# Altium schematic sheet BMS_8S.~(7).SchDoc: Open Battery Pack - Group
size A3; Author: Morgane Vallée; Revision: 1.0; SheetNumber: 2; SheetTotal: 3
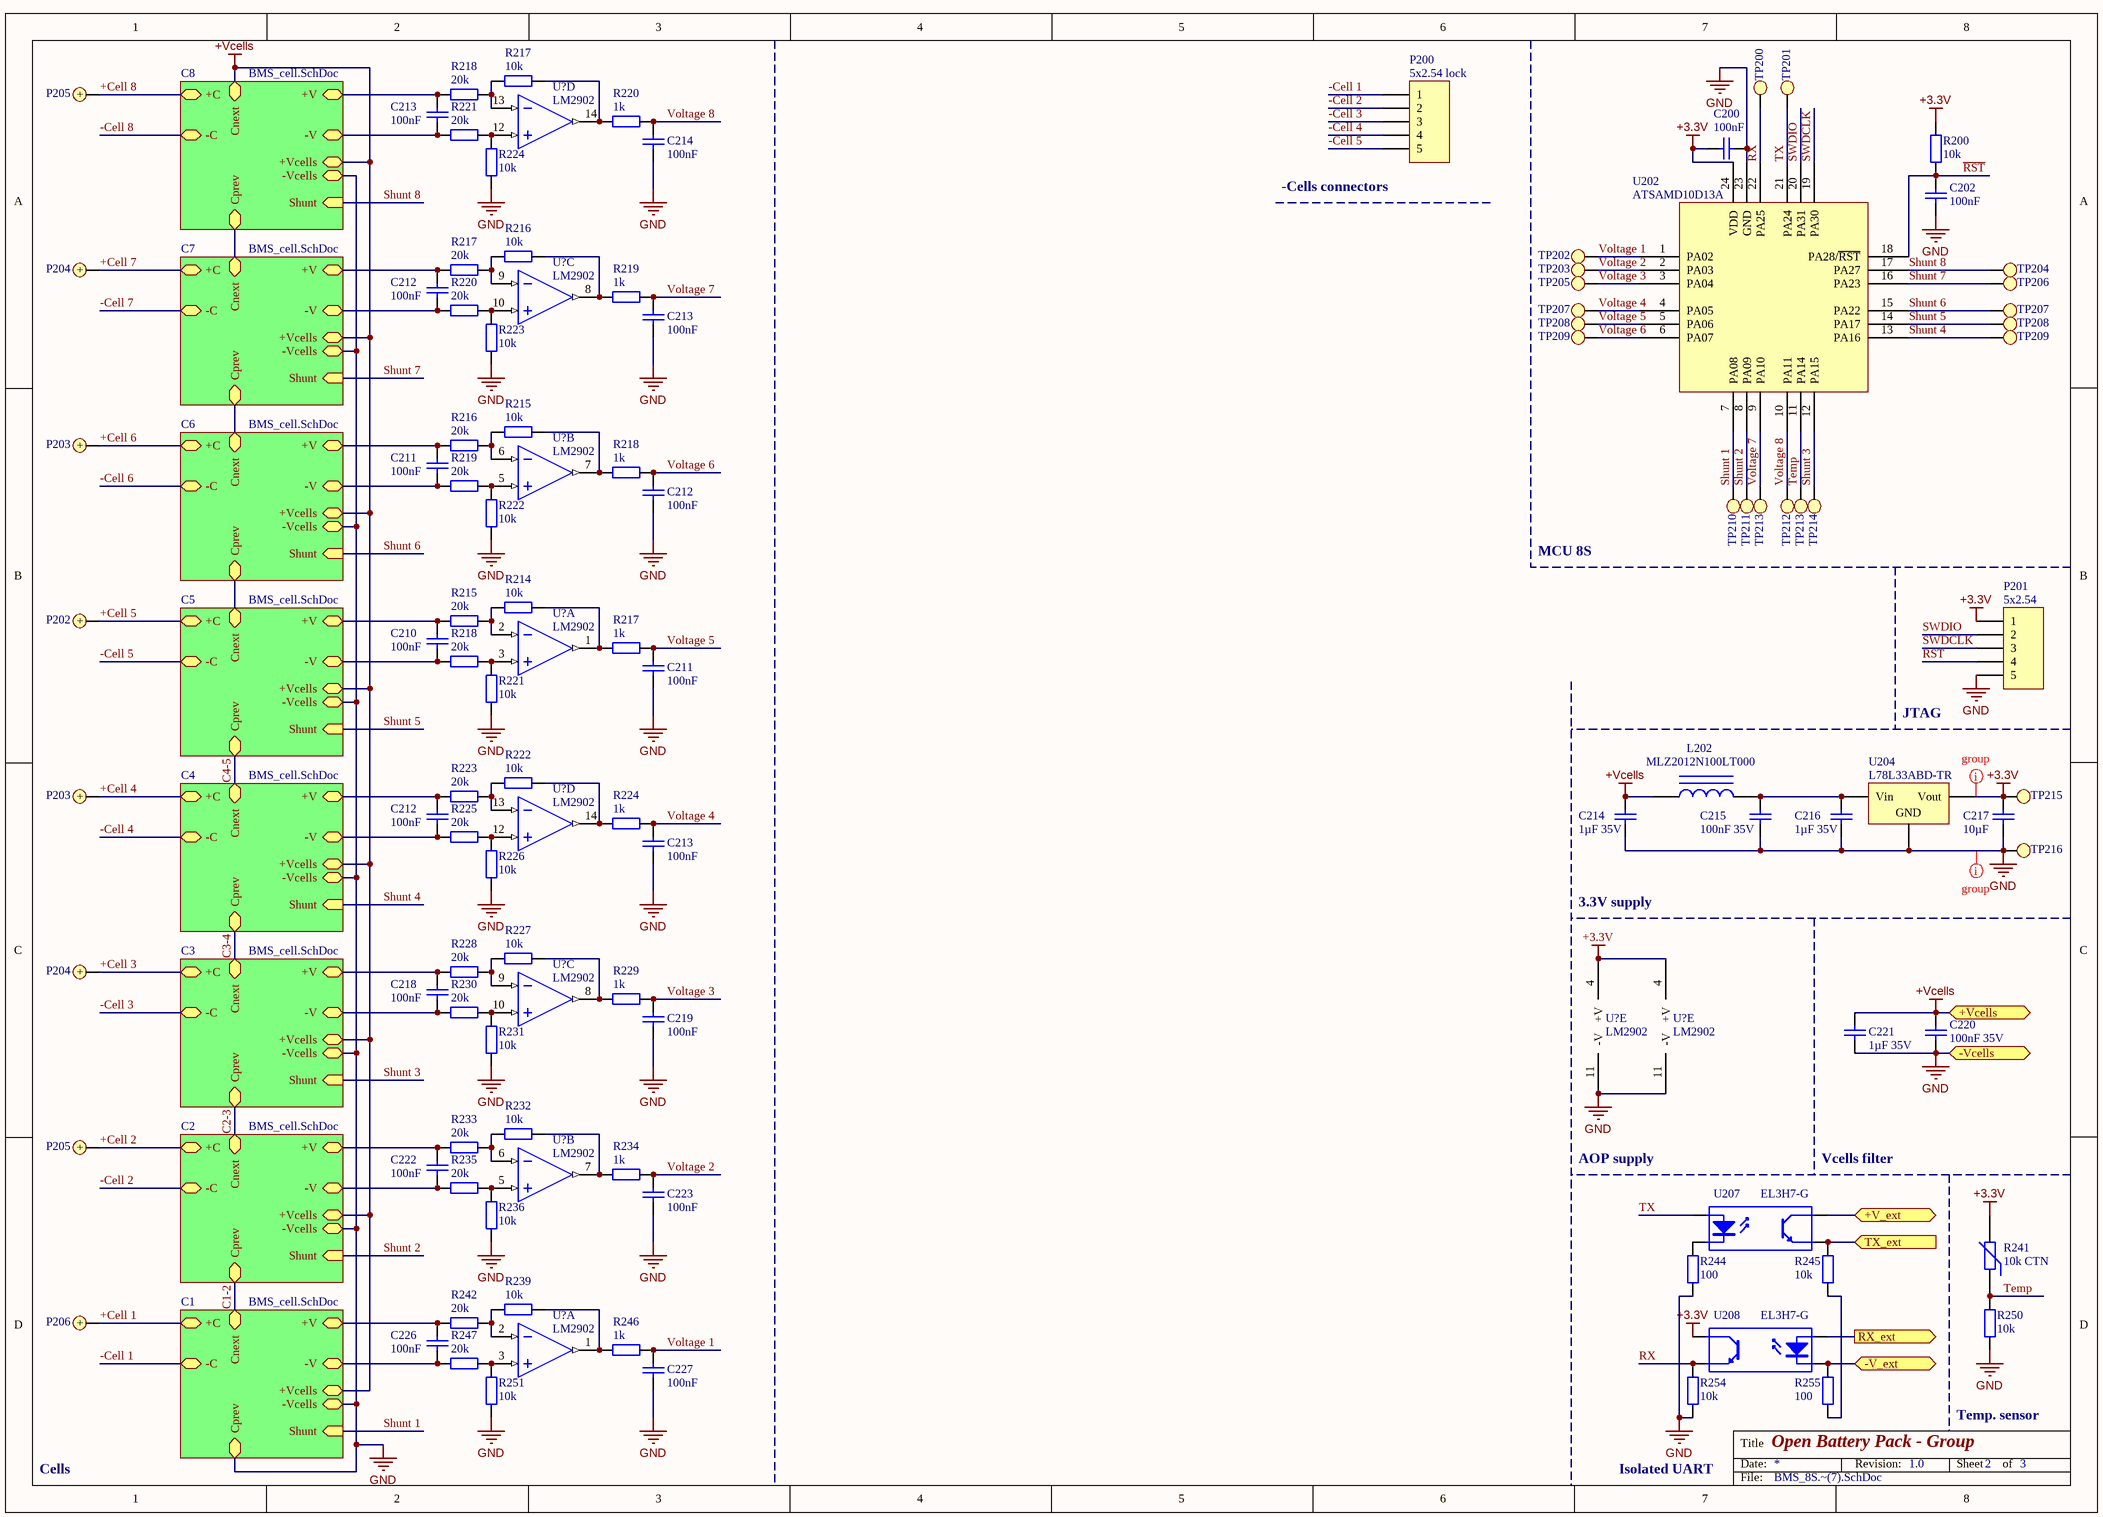
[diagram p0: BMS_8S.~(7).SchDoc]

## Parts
(Parts that share a designator on the sheet are numbered #1, #2 ... from top to bottom, then left to right.)
C200  100nF  [C0603]
C202  100nF  [C0603]
C210  100nF  [C0603]
C211#1  100nF  [C0603]
C211#2  100nF  [C0603]
C212#1  100nF  [C0603]
C212#2  100nF  [C0603]
C212#3  100nF  [C0603]
C213#1  100nF  [C0603]
C213#2  100nF  [C0603]
C213#3  100nF  [C0603]
C214#1  100nF  [C0603]
C214#2  1µF 35V  [C0805]
C215  100nF 35V  [C0603]
C216  1µF 35V  [C0805]
C217  10µF  [C0603]
C218  100nF  [C0603]
C219  100nF  [C0603]
C220  100nF 35V  [C0603]
C221  1µF 35V  [C0805]
C222  100nF  [C0603]
C223  100nF  [C0603]
C226  100nF  [C0603]
C227  100nF  [C0603]
L202  MLZ2012N100LT000  [FER 0805/2012]
P200  5x2.54 lock  [MOLEX KK 0022272051]
P201  5x2.54  [HDR1X5]
P202  Bat+  [Keystone 241]  (value not drawn)
P203#1  Bat+  [Keystone 241]  (value not drawn)
P203#2  Bat+  [Keystone 241]  (value not drawn)
P204#1  Bat+  [Keystone 241]  (value not drawn)
P204#2  Bat+  [Keystone 241]  (value not drawn)
P205#1  Bat+  [Keystone 241]  (value not drawn)
P205#2  Bat+  [Keystone 241]  (value not drawn)
P206  Bat+  [Keystone 241]  (value not drawn)
R200  10k  [R0603]
R214  10k  [R0603]
R215#1  10k  [R0603]
R215#2  20k  [R0603]
R216#1  10k  [R0603]
R216#2  20k  [R0603]
R217#1  10k  [R0603]
R217#2  20k  [R0603]
R217#3  1k  [R0603]
R218#1  20k  [R0603]
R218#2  1k  [R0603]
R218#3  20k  [R0603]
R219#1  1k  [R0603]
R219#2  20k  [R0603]
R220#1  1k  [R0603]
R220#2  20k  [R0603]
R221#1  20k  [R0603]
R221#2  10k  [R0603]
R222#1  10k  [R0603]
R222#2  10k  [R0603]
R223#1  10k  [R0603]
R223#2  20k  [R0603]
R224#1  10k  [R0603]
R224#2  1k  [R0603]
R225  20k  [R0603]
R226  10k  [R0603]
R227  10k  [R0603]
R228  20k  [R0603]
R229  1k  [R0603]
R230  20k  [R0603]
R231  10k  [R0603]
R232  10k  [R0603]
R233  20k  [R0603]
R234  1k  [R0603]
R235  20k  [R0603]
R236  10k  [R0603]
R239  10k  [R0603]
R241  10k CTN  [NTC 0402/1005]
R242  20k  [R0603]
R244  100  [R0603]
R245  10k  [R0603]
R246  1k  [R0603]
R247  20k  [R0603]
R250  10k  [R0603]
R251  10k  [R0603]
R254  10k  [R0603]
R255  100  [R0603]
TP200  Test Point  [Test Point]  (value not drawn)
TP201  Test Point  [Test Point]  (value not drawn)
TP202  Test Point  [Test Point]  (value not drawn)
TP203  Test Point  [Test Point]  (value not drawn)
TP204  Test Point  [Test Point]  (value not drawn)
TP205  Test Point  [Test Point]  (value not drawn)
TP206  Test Point  [Test Point]  (value not drawn)
TP207#1  Test Point  [Test Point]  (value not drawn)
TP207#2  Test Point  [Test Point]  (value not drawn)
TP208#1  Test Point  [Test Point]  (value not drawn)
TP208#2  Test Point  [Test Point]  (value not drawn)
TP209#1  Test Point  [Test Point]  (value not drawn)
TP209#2  Test Point  [Test Point]  (value not drawn)
TP210  Test Point  [Test Point]  (value not drawn)
TP211  Test Point  [Test Point]  (value not drawn)
TP212  Test Point  [Test Point]  (value not drawn)
TP213#1  Test Point  [Test Point]  (value not drawn)
TP213#2  Test Point  [Test Point]  (value not drawn)
TP214  Test Point  [Test Point]  (value not drawn)
TP215  Test Point  [Test Point]  (value not drawn)
TP216  Test Point  [Test Point]  (value not drawn)
U202  ATSAMD10D13A  [SMSC QFN-24 4x4MM]
U204  L78L33ABD-TR  [ST SOIC-8N]
U207  EL3H7-G  [OPTO_EL3H7-G]
U208  EL3H7-G  [OPTO_EL3H7-G]
U?#1  LM2902  [Atmel SO-14 14S1]  (part D of 5)
U?#2  LM2902  [Atmel SO-14 14S1]  (part C of 5)
U?#3  LM2902  [Atmel SO-14 14S1]  (part B of 5)
U?#4  LM2902  [Atmel SO-14 14S1]  (part A of 5)
U?#5  LM2902  [Atmel SO-14 14S1]  (part D of 5)
U?#6  LM2902  [Atmel SO-14 14S1]  (part C of 5)
U?#7  LM2902  [Atmel SO-14 14S1]  (part E of 5)
U?#8  LM2902  [Atmel SO-14 14S1]  (part E of 5)
U?#9  LM2902  [Atmel SO-14 14S1]  (part B of 5)
U?#10  LM2902  [Atmel SO-14 14S1]  (part A of 5)

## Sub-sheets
C1 = BMS_cell.SchDoc: -C, -V, +C, +Vcells, Cnext, -Vcells, +V, Shunt (in), Cprev
C2 = BMS_cell.SchDoc: -C, -V, +C, +Vcells, Cnext, -Vcells, +V, Shunt (in), Cprev
C3 = BMS_cell.SchDoc: -C, -V, +C, +Vcells, Cnext, -Vcells, +V, Shunt (in), Cprev
C4 = BMS_cell.SchDoc: -C, -V, +C, +Vcells, Cnext, -Vcells, +V, Shunt (in), Cprev
C5 = BMS_cell.SchDoc: -C, -V, +C, +Vcells, Cnext, -Vcells, +V, Shunt (in), Cprev
C6 = BMS_cell.SchDoc: -C, -V, +C, +Vcells, Cnext, -Vcells, +V, Shunt (in), Cprev
C7 = BMS_cell.SchDoc: -C, -V, +C, +Vcells, Cnext, -Vcells, +V, Shunt (in), Cprev
C8 = BMS_cell.SchDoc: -C, -V, +C, +Vcells, Cnext, -Vcells, +V, Shunt (in), Cprev

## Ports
+V_ext, +Vcells, -V_ext, -Vcells, RX_ext (out), TX_ext (in)

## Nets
+3.3V: C200.2 C217.1 P201.1 R200.2 R241.2 TP215.1 U202.24(VDD) U204.3(Vout) U208.4(C) U?#7.4(+V) U?#8.4(+V)
+Vcells: C214#2.1 C220.1 C221.1 L202.1 ; port +Vcells, sheet C1/+Vcells, sheet C2/+Vcells, sheet C3/+Vcells, sheet C4/+Vcells, sheet C5/+Vcells, sheet C6/+Vcells, sheet C7/+Vcells, sheet C8/+Vcells, sheet C8/Cnext
GND: C200.1 C202.1 C211#2.2 C212#2.2 C213#2.2 C213#3.2 C214#1.2 C214#2.2 C215.2 C216.2 C217.2 C219.2 C220.2 C221.2 C223.2 C227.2 P201.5 R221#2.2 R222#1.2 R223#1.2 R224#1.2 R226.2 R231.2 R236.2 R244.1 R250.2 R251.2 R254.1 TP216.1 U202.23(GND) U204.2(GND) U?#7.11(-V) U?#8.11(-V) ; port -Vcells, sheet C1/-Vcells, sheet C1/Cprev, sheet C2/-Vcells, sheet C3/-Vcells, sheet C4/-Vcells, sheet C5/-Vcells, sheet C6/-Vcells, sheet C7/-Vcells, sheet C8/-Vcells
+Cell 1: P206.1 ; sheet C1/+C
+Cell 2: P205#2.1 ; sheet C2/+C
+Cell 3: P204#2.1 ; sheet C3/+C
+Cell 4: P203#2.1 ; sheet C4/+C
+Cell 5: P202.1 ; sheet C5/+C
+Cell 6: P203#1.1 ; sheet C6/+C
+Cell 7: P204#1.1 ; sheet C7/+C
+Cell 8: P205#1.1 ; sheet C8/+C
+V_ext: U207.4(C) ; port +V_ext
-Cell 1: P200.1 ; sheet C1/-C
-Cell 2: P200.2 ; sheet C2/-C
-Cell 3: P200.3 ; sheet C3/-C
-Cell 4: P200.4 ; sheet C4/-C
-Cell 5: P200.5 ; sheet C5/-C
-V_ext: R255.1 U208.2(K) ; port -V_ext
C1-2: sheet C1/Cnext, sheet C2/Cprev
C2-3: sheet C2/Cnext, sheet C3/Cprev
C3-4: sheet C3/Cnext, sheet C4/Cprev
C4-5: sheet C4/Cnext, sheet C5/Cprev
~{RST}: C202.2 P201.4 R200.1 U202.18(PA28/~{RST})
RX: R254.2 TP200.1 U202.22(PA25) U208.3(E)
RX_ext: U208.1(A) ; port RX_ext
Shunt 1: TP210.1 U202.7(PA08) ; sheet C1/Shunt
Shunt 2: TP211.1 U202.8(PA09) ; sheet C2/Shunt
Shunt 3: TP214.1 U202.12(PA15) ; sheet C3/Shunt
Shunt 4: TP209#2.1 U202.13(PA16) ; sheet C4/Shunt
Shunt 5: TP208#2.1 U202.14(PA17) ; sheet C5/Shunt
Shunt 6: TP207#2.1 U202.15(PA22) ; sheet C6/Shunt
Shunt 7: TP206.1 U202.16(PA23) ; sheet C7/Shunt
Shunt 8: TP204.1 U202.17(PA27) ; sheet C8/Shunt
SWDCLK: P201.3 U202.19(PA30)
SWDIO: P201.2 U202.20(PA31)
Temp: R241.1 R250.1 TP213#2.1 U202.11(PA14)
TX: TP201.1 U202.21(PA24) U207.1(A)
TX_ext: R245.1 U207.3(E) ; port TX_ext
Voltage 1: C227.1 R246.1 TP202.1 U202.1(PA02)
Voltage 2: C223.1 R234.1 TP203.1 U202.2(PA03)
Voltage 3: C219.1 R229.1 TP205.1 U202.3(PA04)
Voltage 4: C213#3.1 R224#2.1 TP207#1.1 U202.4(PA05)
Voltage 5: C211#2.1 R217#3.1 TP208#1.1 U202.5(PA06)
Voltage 6: C212#2.1 R218#2.1 TP209#1.1 U202.6(PA07)
Voltage 7: C213#2.1 R219#1.1 TP213#1.1 U202.9(PA10)
Voltage 8: C214#1.1 R220#1.1 TP212.1 U202.10(PA11)
NetC210_1: C210.1 R215#2.1 ; sheet C5/+V
NetC210_2: C210.2 R218#3.2 ; sheet C5/-V
NetC211#1_1: C211#1.1 R216#2.1 ; sheet C6/+V
NetC211#1_2: C211#1.2 R219#2.2 ; sheet C6/-V
NetC212#1_1: C212#1.1 R217#2.1 ; sheet C7/+V
NetC212#1_2: C212#1.2 R220#2.2 ; sheet C7/-V
NetC212#3_1: C212#3.1 R223#2.1 ; sheet C4/+V
NetC212#3_2: C212#3.2 R225.2 ; sheet C4/-V
NetC213#1_1: C213#1.1 R218#1.1 ; sheet C8/+V
NetC213#1_2: C213#1.2 R221#1.2 ; sheet C8/-V
NetC215_1: C215.1 C216.1 L202.2 U204.1(Vin)
NetC218_1: C218.1 R228.1 ; sheet C3/+V
NetC218_2: C218.2 R230.2 ; sheet C3/-V
NetC222_1: C222.1 R233.1 ; sheet C2/+V
NetC222_2: C222.2 R235.2 ; sheet C2/-V
NetC226_1: C226.1 R242.1 ; sheet C1/+V
NetC226_2: C226.2 R247.2 ; sheet C1/-V
NetR214_1: R214.1 R215#2.2 U?#4.2(IN-)
NetR214_2: R214.2 R217#3.2 U?#4.1(OUT)
NetR215#1_1: R215#1.1 R216#2.2 U?#3.6(IN-)
NetR215#1_2: R215#1.2 R218#2.2 U?#3.7(OUT)
NetR216#1_1: R216#1.1 R217#2.2 U?#2.9(IN-)
NetR216#1_2: R216#1.2 R219#1.2 U?#2.8(OUT)
NetR217#1_1: R217#1.1 R218#1.2 U?#1.13(IN-)
NetR217#1_2: R217#1.2 R220#1.2 U?#1.14(OUT)
NetR218#3_1: R218#3.1 R221#2.1 U?#4.3(IN+)
NetR219#2_1: R219#2.1 R222#1.1 U?#3.5(IN+)
NetR220#2_1: R220#2.1 R223#1.1 U?#2.10(IN+)
NetR221#1_1: R221#1.1 R224#1.1 U?#1.12(IN+)
NetR222#2_1: R222#2.1 R223#2.2 U?#5.13(IN-)
NetR222#2_2: R222#2.2 R224#2.2 U?#5.14(OUT)
NetR225_1: R225.1 R226.1 U?#5.12(IN+)
NetR227_1: R227.1 R228.2 U?#6.9(IN-)
NetR227_2: R227.2 R229.2 U?#6.8(OUT)
NetR230_1: R230.1 R231.1 U?#6.10(IN+)
NetR232_1: R232.1 R233.2 U?#9.6(IN-)
NetR232_2: R232.2 R234.2 U?#9.7(OUT)
NetR235_1: R235.1 R236.1 U?#9.5(IN+)
NetR239_1: R239.1 R242.2 U?#10.2(IN-)
NetR239_2: R239.2 R246.2 U?#10.1(OUT)
NetR244_2: R244.2 U207.2(K)
NetR245_2: R245.2 R255.2
NetR247_1: R247.1 R251.1 U?#10.3(IN+)
(unnamed): sheet C5/Cnext, sheet C6/Cprev
(unnamed): sheet C6/Cnext, sheet C7/Cprev  [a separate net that carries the same name]
(unnamed): sheet C7/Cnext, sheet C8/Cprev  [a separate net that carries the same name]

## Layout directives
net class Group: +3.3V, GND

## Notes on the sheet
- (near P200) -Cells connectors
- MCU 8S
- JTAG
- 3.3V supply
- AOP supply
- (near U207) Vcells filter
- Temp. sensor
- Cells
- Isolated UART

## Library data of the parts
C200 C202 C210 C211#1 C211#2 C212#1-C212#3 C213#1-C213#3 C214#1 C214#2 C215-C223 C226 C227 = Cap: Capacitor
L202 = Inductor Iron: Magnetic-Core Inductor
P200 P201 = Header 5: Header, 5-Pin
P202 P203#1 P203#2 P204#1 P204#2 P205#1 P205#2 P206 = Bat+: Battery contact +
R200 R214 R215#1 R215#2 R216#1 R216#2 R217#1-R217#3 R218#1-R218#3 R219#1 R219#2 R220#1 R220#2 R221#1 R221#2 R222#1 R222#2 R223#1 R223#2 R224#1 R224#2 R225-R236 R239 R242 R244-R247 R250 R251 R254 R255 = Res2: Resistor
R241 = Res Varistor: Varistor (Voltage-Sensitive Resistor)
U204 = Volt Reg: Voltage Regulator; pin to pad: 1>8 2>2+3+6+7 3>1
U207 U208 = Optoisolator1: 4-Pin Phototransistor Optocoupler
U?#1-U?#10 = LM2902: Low-power quad operational amplifiers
